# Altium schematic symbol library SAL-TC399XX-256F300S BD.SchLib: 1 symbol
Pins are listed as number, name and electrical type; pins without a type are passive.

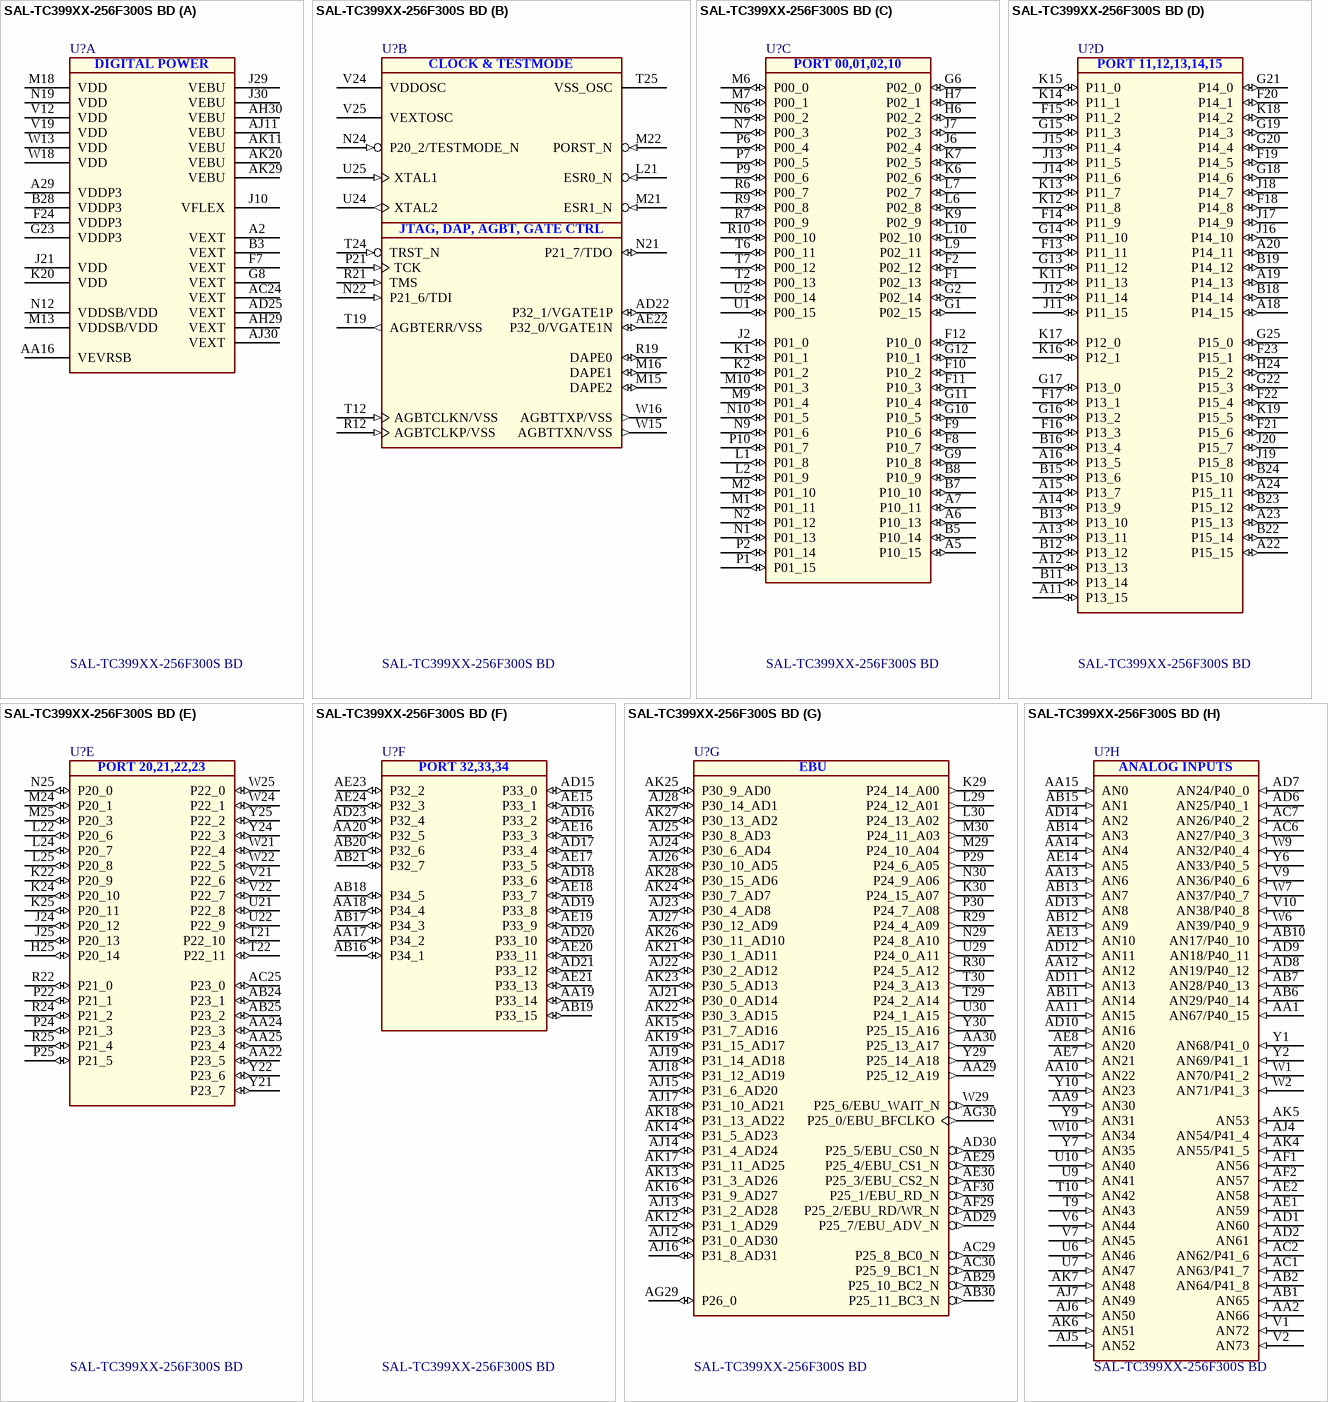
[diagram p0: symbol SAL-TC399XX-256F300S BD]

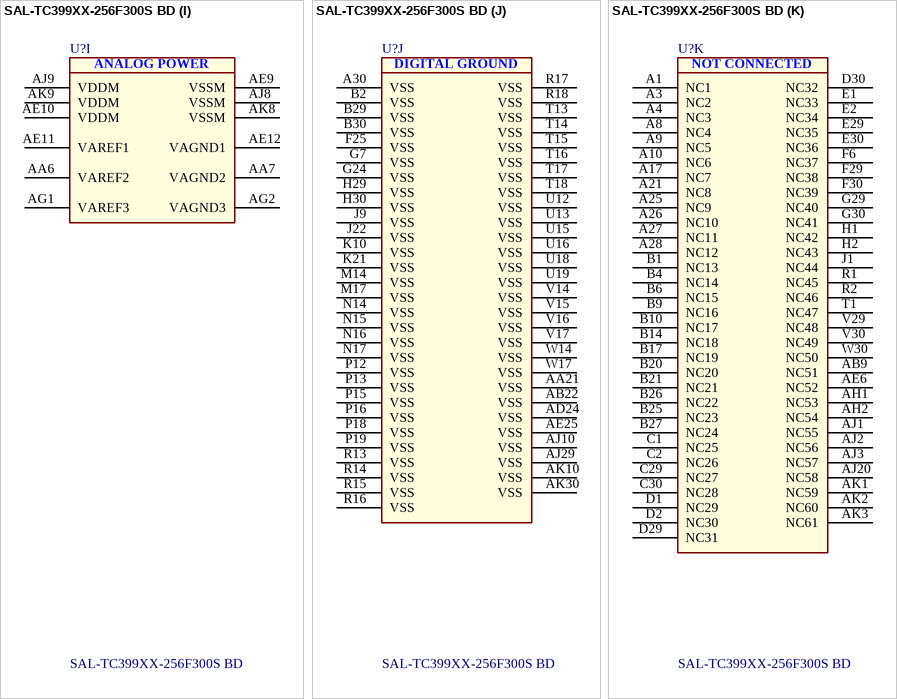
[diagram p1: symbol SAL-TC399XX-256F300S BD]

## SAL-TC399XX-256F300S BD
designator U?
TC39xA_BGA516 Pins; Manufacturer: Infineon Technologies
part A pins: A2 VEXT (power), A29 VDDP3 (power), AA16 VEVRSB (power), AC24 VEXT (power), AD25 VEXT (power), AH29 VEXT (power), AH30 VEBU (power), AJ11 VEBU (power), AJ30 VEXT (power), AK11 VEBU (power), AK20 VEBU (power), AK29 VEBU (power), B3 VEXT (power), B28 VDDP3 (power), F7 VEXT (power), F24 VDDP3 (power), G8 VEXT (power), G23 VDDP3 (power), J10 VFLEX (power), J21 VDD (power), J29 VEBU (power), J30 VEBU (power), K20 VDD (power), M13 VDDSB/VDD (power), M18 VDD (power), N12 VDDSB/VDD (power), N19 VDD (power), V12 VDD (power), V19 VDD (power), W13 VDD (power), W18 VDD (power)
part B pins: AD22 P32_1/VGATE1P (io), AE22 P32_0/VGATE1N (io), L21 ESR0_N (in), M15 DAPE2 (io), M16 DAPE1 (io), M21 ESR1_N (in), M22 PORST_N (in), N21 P21_7/TDO (io), N22 P21_6/TDI (in), N24 P20_2/TESTMODE_N (in), P21 TCK (in), R12 AGBTCLKP/VSS (in), R19 DAPE0 (io), R21 TMS (in), T12 AGBTCLKN/VSS (in), T19 AGBTERR/VSS (out), T24 TRST_N (in), T25 VSS_OSC (power), U24 XTAL2 (out), U25 XTAL1 (in), V24 VDDOSC (power), V25 VEXTOSC (power), W15 AGBTTXN/VSS (out), W16 AGBTTXP/VSS (out)
part C pins: A5 P10_15 (io), A6 P10_13 (io), A7 P10_11 (io), B5 P10_14 (io), B7 P10_10 (io), B8 P10_9 (io), F1 P02_13 (io), F2 P02_12 (io), F8 P10_7 (io), F9 P10_6 (io), F10 P10_2 (io), F11 P10_3 (io), F12 P10_0 (io), G1 P02_15 (io), G2 P02_14 (io), G6 P02_0 (io), G9 P10_8 (io), G10 P10_5 (io), G11 P10_4 (io), G12 P10_1 (io), H6 P02_2 (io), H7 P02_1 (io), J2 P01_0 (io), J6 P02_4 (io), J7 P02_3 (io), K1 P01_1 (io), K2 P01_2 (io), K6 P02_6 (io), K7 P02_5 (io), K9 P02_9 (io), L1 P01_8 (io), L2 P01_9 (io), L6 P02_8 (io), L7 P02_7 (io), L9 P02_11 (io), L10 P02_10 (io), M1 P01_11 (io), M2 P01_10 (io), M6 P00_0 (io), M7 P00_1 (io), M9 P01_4 (io), M10 P01_3 (io), N1 P01_13 (io), N2 P01_12 (io), N6 P00_2 (io), N7 P00_3 (io), N9 P01_6 (io), N10 P01_5 (io), P1 P01_15 (io), P2 P01_14 (io), P6 P00_4 (io), P7 P00_5 (io), P9 P00_6 (io), P10 P01_7 (io), R6 P00_7 (io), R7 P00_9 (io), R9 P00_8 (io), R10 P00_10 (io), T2 P00_13 (io), T6 P00_11 (io), T7 P00_12 (io), U1 P00_15 (io), U2 P00_14 (io)
part D pins: A11 P13_15 (io), A12 P13_13 (io), A13 P13_11 (io), A14 P13_9 (io), A15 P13_7 (io), A16 P13_5 (io), A18 P14_15 (io), A19 P14_13 (io), A20 P14_11 (io), A22 P15_15 (io), A23 P15_13 (io), A24 P15_11 (io), B11 P13_14 (io), B12 P13_12 (io), B13 P13_10 (io), B15 P13_6 (io), B16 P13_4 (io), B18 P14_14 (io), B19 P14_12 (io), B22 P15_14 (io), B23 P15_12 (io), B24 P15_10 (io), F13 P11_11 (io), F14 P11_9 (io), F15 P11_2 (io), F16 P13_3 (io), F17 P13_1 (io), F18 P14_8 (io), F19 P14_5 (io), F20 P14_1 (io), F21 P15_6 (io), F22 P15_4 (io), F23 P15_1 (io), G13 P11_12 (io), G14 P11_10 (io), G15 P11_3 (io), G16 P13_2 (io), G17 P13_0 (io), G18 P14_6 (io), G19 P14_3 (io), G20 P14_4 (io), G21 P14_0 (io), G22 P15_3 (io), G25 P15_0 (io), H24 P15_2 (io), J11 P11_15 (io), J12 P11_14 (io), J13 P11_5 (io), J14 P11_6 (io), J15 P11_4 (io), J16 P14_10 (io), J17 P14_9 (io), J18 P14_7 (io), J19 P15_8 (io), J20 P15_7 (io), K11 P11_13 (io), K12 P11_8 (io), K13 P11_7 (io), K14 P11_1 (io), K15 P11_0 (io), K16 P12_1 (io), K17 P12_0 (io), K18 P14_2 (io), K19 P15_5 (io)
part E pins: AA22 P23_5 (io), AA24 P23_3 (io), AA25 P23_4 (io), AB24 P23_1 (io), AB25 P23_2 (io), AC25 P23_0 (io), H25 P20_14 (io), J24 P20_12 (io), J25 P20_13 (io), K22 P20_9 (io), K24 P20_10 (io), K25 P20_11 (io), L22 P20_6 (io), L24 P20_7 (io), L25 P20_8 (io), M24 P20_1 (io), M25 P20_3 (io), N25 P20_0 (io), P22 P21_1 (io), P24 P21_3 (io), P25 P21_5 (io), R22 P21_0 (io), R24 P21_2 (io), R25 P21_4 (io), T21 P22_10 (io), T22 P22_11 (io), U21 P22_8 (io), U22 P22_9 (io), V21 P22_6 (io), V22 P22_7 (io), W21 P22_4 (io), W22 P22_5 (io), W24 P22_1 (io), W25 P22_0 (io), Y21 P23_7 (io), Y22 P23_6 (io), Y24 P22_3 (io), Y25 P22_2 (io)
part F pins: AA17 P34_2 (io), AA18 P34_4 (io), AA19 P33_14 (io), AA20 P32_5 (io), AB16 P34_1 (io), AB17 P34_3 (io), AB18 P34_5 (io), AB19 P33_15 (io), AB20 P32_6 (io), AB21 P32_7 (io), AD15 P33_0 (io), AD16 P33_2 (io), AD17 P33_4 (io), AD18 P33_6 (io), AD19 P33_8 (io), AD20 P33_10 (io), AD21 P33_12 (io), AD23 P32_4 (io), AE15 P33_1 (io), AE16 P33_3 (io), AE17 P33_5 (io), AE18 P33_7 (io), AE19 P33_9 (io), AE20 P33_11 (io), AE21 P33_13 (io), AE23 P32_2 (io), AE24 P32_3 (io)
part G pins: AA29 P25_12_A19 (out), AA30 P25_13_A17 (out), AB29 P25_10_BC2_N (out), AB30 P25_11_BC3_N (out), AC29 P25_8_BC0_N (out), AC30 P25_9_BC1_N (out), AD29 P25_7/EBU_ADV_N (out), AD30 P25_5/EBU_CS0_N (out), AE29 P25_4/EBU_CS1_N (out), AE30 P25_3/EBU_CS2_N (out), AF29 P25_2/EBU_RD/WR_N (out), AF30 P25_1/EBU_RD_N (out), AG29 P26_0 (io), AG30 P25_0/EBU_BFCLKO (out), AJ12 P31_0_AD30 (io), AJ13 P31_2_AD28 (io), AJ14 P31_4_AD24 (io), AJ15 P31_6_AD20 (io), AJ16 P31_8_AD31 (io), AJ17 P31_10_AD21 (io), AJ18 P31_12_AD19 (io), AJ19 P31_14_AD18 (io), AJ21 P30_0_AD14 (io), AJ22 P30_2_AD12 (io), AJ23 P30_4_AD8 (io), AJ24 P30_6_AD4 (io), AJ25 P30_8_AD3 (io), AJ26 P30_10_AD5 (io), AJ27 P30_12_AD9 (io), AJ28 P30_14_AD1 (io), AK12 P31_1_AD29 (io), AK13 P31_3_AD26 (io), AK14 P31_5_AD23 (io), AK15 P31_7_AD16 (io), AK16 P31_9_AD27 (io), AK17 P31_11_AD25 (io), AK18 P31_13_AD22 (io), AK19 P31_15_AD17 (io), AK21 P30_1_AD11 (io), AK22 P30_3_AD15 (io), AK23 P30_5_AD13 (io), AK24 P30_7_AD7 (io), AK25 P30_9_AD0 (io), AK26 P30_11_AD10 (io), AK27 P30_13_AD2 (io), AK28 P30_15_AD6 (io), K29 P24_14_A00 (out), K30 P24_15_A07 (out), L29 P24_12_A01 (out), L30 P24_13_A02 (out), M29 P24_10_A04 (out), M30 P24_11_A03 (out), N29 P24_8_A10 (out), N30 P24_9_A06 (out), P29 P24_6_A05 (out), P30 P24_7_A08 (out), R29 P24_4_A09 (out), R30 P24_5_A12 (out), T29 P24_2_A14 (out), T30 P24_3_A13 (out), U29 P24_0_A11 (out), U30 P24_1_A15 (out), W29 P25_6/EBU_WAIT_N (out), Y29 P25_14_A18 (out), Y30 P25_15_A16 (out)
part H pins: AA1 AN67/P40_15 (in), AA2 AN66 (in), AA9 AN30 (in), AA10 AN22 (in), AA11 AN15 (in), AA12 AN12 (in), AA13 AN6 (in), AA14 AN4 (in), AA15 AN0 (in), AB1 AN65 (in), AB2 AN64/P41_8 (in), AB6 AN29/P40_14 (in), AB7 AN28/P40_13 (in), AB10 AN17/P40_10 (in), AB11 AN14 (in), AB12 AN9 (in), AB13 AN7 (in), AB14 AN3 (in), AB15 AN1 (in), AC1 AN63/P41_7 (in), AC2 AN62/P41_6 (in), AC6 AN27/P40_3 (in), AC7 AN26/P40_2 (in), AD1 AN60 (in), AD2 AN61 (in), AD6 AN25/P40_1 (in), AD7 AN24/P40_0 (in), AD8 AN19/P40_12 (in), AD9 AN18/P40_11 (in), AD10 AN16 (in), AD11 AN13 (in), AD12 AN11 (in), AD13 AN8 (in), AD14 AN2 (in), AE1 AN59 (in), AE2 AN58 (in), AE7 AN21 (in), AE8 AN20 (in), AE13 AN10 (in), AE14 AN5 (in), AF1 AN56 (in), AF2 AN57 (in), AJ4 AN54/P41_4 (in), AJ5 AN52 (in), AJ6 AN50 (in), AJ7 AN49 (in), AK4 AN55/P41_5 (in), AK5 AN53 (in), AK6 AN51 (in), AK7 AN48 (in), T9 AN43 (in), T10 AN42 (in), U6 AN46 (in), U7 AN47 (in), U9 AN41 (in), U10 AN40 (in), V1 AN72 (in), V2 AN73 (in), V6 AN44 (in), V7 AN45 (in), V9 AN36/P40_6 (in), V10 AN38/P40_8 (in), W1 AN70/P41_2 (in), W2 AN71/P41_3 (in), W6 AN39/P40_9 (in), W7 AN37/P40_7 (in), W9 AN32/P40_4 (in), W10 AN34 (in), Y1 AN68/P41_0 (in), Y2 AN69/P41_1 (in), Y6 AN33/P40_5 (in), Y7 AN35 (in), Y9 AN31 (in), Y10 AN23 (in)
part I pins: AA6 VAREF2 (power), AA7 VAGND2 (power), AE9 VSSM (power), AE10 VDDM (power), AE11 VAREF1 (power), AE12 VAGND1 (power), AG1 VAREF3 (power), AG2 VAGND3 (power), AJ8 VSSM (power), AJ9 VDDM (power), AK8 VSSM (power), AK9 VDDM (power)
part J pins: A30 VSS (power), AA21 VSS (power), AB22 VSS (power), AD24 VSS (power), AE25 VSS (power), AJ10 VSS (power), AJ29 VSS (power), AK10 VSS (power), AK30 VSS (power), B2 VSS (power), B29 VSS (power), B30 VSS (power), F25 VSS (power), G7 VSS (power), G24 VSS (power), H29 VSS (power), H30 VSS (power), J9 VSS (power), J22 VSS (power), K10 VSS (power), K21 VSS (power), M14 VSS (power), M17 VSS (power), N14 VSS (power), N15 VSS (power), N16 VSS (power), N17 VSS (power), P12 VSS (power), P13 VSS (power), P15 VSS (power), P16 VSS (power), P18 VSS (power), P19 VSS (power), R13 VSS (power), R14 VSS (power), R15 VSS (power), R16 VSS (power), R17 VSS (power), R18 VSS (power), T13 VSS (power), T14 VSS (power), T15 VSS (power), T16 VSS (power), T17 VSS (power), T18 VSS (power), U12 VSS (power), U13 VSS (power), U15 VSS (power), U16 VSS (power), U18 VSS (power), U19 VSS (power), V14 VSS (power), V15 VSS (power), V16 VSS (power), V17 VSS (power), W14 VSS (power), W17 VSS (power)
part K pins: A1 NC1, A3 NC2, A4 NC3, A8 NC4, A9 NC5, A10 NC6, A17 NC7, A21 NC8, A25 NC9, A26 NC10, A27 NC11, A28 NC12, AB9 NC51, AE6 NC52, AH1 NC53, AH2 NC54, AJ1 NC55, AJ2 NC56, AJ3 NC57, AJ20 NC58, AK1 NC59, AK2 NC60, AK3 NC61, B1 NC13, B4 NC14, B6 NC15, B9 NC16, B10 NC17, B14 NC18, B17 NC19, B20 NC20, B21 NC21, B25 NC23, B26 NC22, B27 NC24, C1 NC25, C2 NC26, C29 NC27, C30 NC28, D1 NC29, D2 NC30, D29 NC31, D30 NC32, E1 NC33, E2 NC34, E29 NC35, E30 NC36, F6 NC37, F29 NC38, F30 NC39, G29 NC40, G30 NC41, H1 NC42, H2 NC43, J1 NC44, R1 NC45, R2 NC46, T1 NC47, V29 NC48, V30 NC49, W30 NC50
